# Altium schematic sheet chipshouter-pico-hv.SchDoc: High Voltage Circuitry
size Letter; Organization: NewAE Technology Inc.; Address1: 1083 Queen St., Suite 196; Address2: Halifax; Address3: NS; Address4: Canada B3H 0B2; DocumentNumber: .; Revision: .; SheetNumber: 1; SheetTotal: 2; SheetApproved: YES
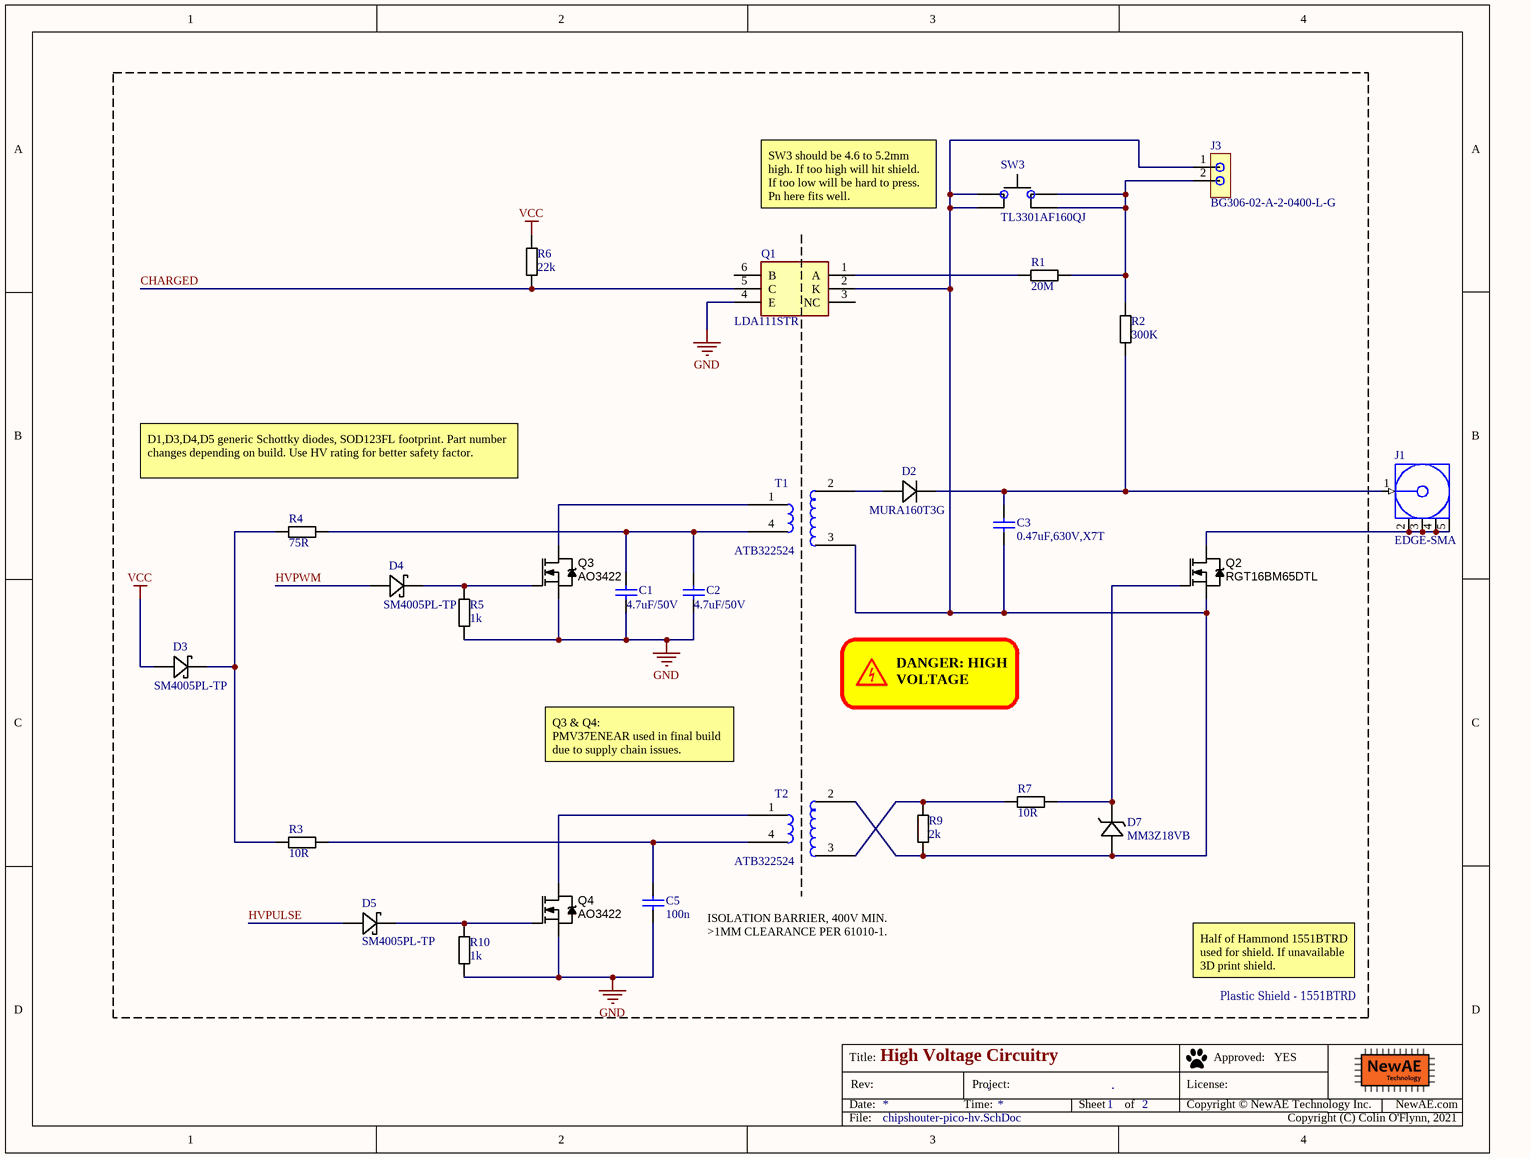
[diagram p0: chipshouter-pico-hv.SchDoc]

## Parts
C1  4.7uF/50V  [CAPC0805_M]
C2  4.7uF/50V  [CAPC0805_M]
C3  0.47uF,630V,X7T  [CKG57N_2220]
C5  100n  [CAPC0603_M]
D2  MURA160T3G  [DO-214AC]
D3  SM4005PL-TP  [DSS13UTR]
D4  SM4005PL-TP  [DSS13UTR]
D5  SM4005PL-TP  [DSS13UTR]
D7  MM3Z18VB  [SOD323]
J1  EDGE-SMA  [CON-SMA-MALE-PCB-EDGE062]
J3  BG306-02-A-2-0400-L-G  [BG306-R2-2PIN]
Q1  LDA111STR  [SOP254P952X470-6N]
Q2  RGT16BM65DTL  [DPAK_TO-252AA_M]
Q3  AO3422  [SOT95P245X110-3M]
Q4  AO3422  [SOT95P245X110-3M]
R1  20M  [RESC5025X06N]
R2  300K  [RESC6432X06N]
R3  10R  [RESC1608X55N]
R4  75R  [RESC2012X70N]
R5  1k  [RESC1608X55N]
R6  22k  [RESC1608X55N]
R7  10R  [RESC1608X55N]
R9  2k  [RESC2012X70N]
R10  1k  [RESC1608X55N]
SW3  TL3301AF160QJ  [CK_KSC7J]
T1  ATB322524  [ATB322524_CHUNKY]
T2  ATB322524  [ATB322524_CHUNKY]

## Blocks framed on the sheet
Plastic Shield - 1551BTRD‎: C1-C3 C5 D2-D5 D7 J3 Q1-Q4 R1-R7 R9 R10 SW3 T1 T2

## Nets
GND: C1.2 C2.2 C5.2 Q1.4(E) Q3.2(S) Q4.2(S) R5.2 R10.2
VCC: D3.A R6.1
CHARGED: Q1.5(C) R6.2
HVPULSE: D5.A
HVPWM: D4.A
NetC1_1: C1.1 C2.1 R4.2 T1.4
NetC3_1: C3.1 D2.K J1.1(Signal) R2.2
NetC3_2: C3.2 D7.A J3.1 Q1.2(K) Q2.2(S) R9.2 SW3.1(IN) SW3.4(IN) T1.3 T2.2
NetC5_1: C5.1 R3.2 T2.4
NetD2_A: D2.A T1.2
NetD3_K: D3.K R3.1 R4.1
NetD4_K: D4.K Q3.1(G) R5.1
NetD5_K: D5.K Q4.1(G) R10.1
NetD7_K: D7.K Q2.1(G) R7.2
NetJ1_2: J1.2(GND) J1.3(GND) J1.4(GND) J1.5(GND) Q2.3(D)
NetJ3_2: J3.2 R1.2 R2.1 SW3.2(IN) SW3.3(IN)
NetQ1_1: Q1.1(A) R1.1
NetQ3_3: Q3.3(D) T1.1
NetQ4_3: Q4.3(D) T2.1
NetR7_1: R7.1 R9.1 T2.3

Not connected (* = marked no-connect by the designer): Q1 3(NC) 6(B)

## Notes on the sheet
- SW3 should be 4.6 to 5.2mm high. If too high will hit shield. If too low will be hard to press. Pn here fits well.
- D1,D3,D4,D5 generic Schottky diodes, SOD123FL footprint. Part number changes depending on build. Use HV rating for better safety factor.
- DANGER: HIGH
  VOLTAGE
- Q3 & Q4:
  PMV37ENEAR used in final build due to supply chain issues.
- ISOLATION BARRIER, 400V MIN.
  >1MM CLEARANCE PER 61010-1.
- Half of Hammond 1551BTRD used for shield. If unavailable 3D print shield.
- Copyright (C) Colin O'Flynn, 2021

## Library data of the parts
C1 C2 = CCHIP-4u7-0805-50V: 4u7, 50V, 0805, Ceramic; Manufacture 1: TDK Corporation; Manufacture Part Number 1: C2012X5R1H475K125AB; Component Group: Capacitor; Value: 4.7uF; Case-EIA: 0805; Case-Metric: 1608; Rated Voltage: 50VDC; Tolerance: 10%
C3 = CKG57NX7T2J105M500JH: 1uF, 630V, X7T, Stacked; Part Number: KRM55TR72J474MH01K; Manufacture 1: TDK Corporation; Component Group: Capacitor; Case-EIA: 2220; Case-Metric: 5750; Tolerance: +22/-30
C5 = CCHIP-100n-0603: 100n, 0603; Manufacture 1: Kemet; Manufacture Part Number 1: C0603C104K5RACTU; Component Group: Capacitor; Case-EIA: 0603; Case-Metric: 1608; Rated Voltage: 50VDC
D2 = MURA160T3G: 600V, 2A, Fast Recovery Diode; Manufacture 1: On Semi
D3-D5 = DSS13UTR: SCHOTTKY 30V SOD-123FL; Manufacture 1: MCC; Component Group: Diode; PP Material Stack: 0
D7 = PDZ10B: DIODE ZENER 10V 400MW SOD323; Manufacture 1: On Semiconductor; Rated Power: 0.4W; Tolerance: 2%; PP Material Stack: 0
J1 = CON-F-SMA-PCBEDGE-003.062: SMA MaleEdge Mount Connector for 0.062" Thick Board; Manufacture 1: Linx Technologies; Manufacture Part Number 1: CONSMA013.062
J3 = BG306-02-A-2-0400-L-G: 2-Pin SMD, Female Header, 0.1" spacing; Manufacture 1: GCT; Component Group: Connector; PP Material Stack: 0
Q1 = LDA111STR: Phototransistor; Manufacturer_Name: IXYS SEMICONDUCTOR
Q2 = IRLR120TRPBF: MOSFET N-CH 100V 7.7A DPAK; Manufacture 1: Vishay Siliconix
Q3 Q4 = DMN3200U-7: MOSFET N-CH 30V 2.2A SOT23-3; Manufacture 1: Diodes Inc.; Rated Power: 3A; PP Material Stack: 0
R1 = RCHIP-20M-2010: 20M, 2010, 1%; Manufacture 1: Vishay; Manufacture Part Number 1: CRMA2010AF20M0FKEF; Component Group: Resistor; Case-EIA: 2010; Case-Metric: 5025; Rated Power: 0.5W; Rated Voltage: 400VDC
R2 = RCHIP-300K-2512: 300K res, 2512, 1%, 3W; Manufacture 1: TE Connectivity; Manufacture Part Number 1: 3522300KFT; Component Group: Resistor; Case-EIA: 2512; Case-Metric: 6432; Rated Voltage: 250V
R3 R7 = RCHIP-10R-0603: 10R res, 0603, 1%, 1/10W; Manufacture 1: Yageo; Manufacture Part Number 1: RC0603FR-0710RL; Component Group: Resistor; Case-EIA: 0603; Case-Metric: 1608; Rated Power: 0.1W; Rated Voltage: 75VDC
R4 = RCHIP-75R-0805: 75R res, 0805, 1%, 1/8W; Manufacture 1: Yageo; Manufacture Part Number 1: RC0805FR-0775RL; Component Group: Resistor; Case-EIA: 0805; Rated Power: 0.125W; Rated Voltage: 75VDC
R5 R10 = RCHIP-1K-0603: 1k res, 0603, 1%, 1/10W; Manufacture 1: Yageo; Manufacture Part Number 1: RC0603FR-071KL; Component Group: Resistor; Case-EIA: 0603; Case-Metric: 1608; Rated Power: 0.1W; Rated Voltage: 75VDC
R6 = RCHIP-22K-0603: 22k res, 0603, 1%, 1/10W; Manufacture 1: Yageo; Manufacture Part Number 1: RC0603FR-0722KL; Component Group: Resistor; Case-EIA: 0603; Case-Metric: 1608; Rated Power: 0.1W; Rated Voltage: 75VDC
R9 = RCHIP-75R-0805: Manufacture 1: Yageo; Manufacture Part Number 1: RC0805FR-0775RL; Component Group: Resistor; Value: 75R; Case-EIA: 0805; Rated Power: 0.125W; Rated Voltage: 75VDC; Tolerance: 1%
SW3 = TACTSW-KSC741J: SWITCH TACTILE SPST-NO 0.01A 32V; Manufacture 1: E-Switch; PP Material Stack: 0
T1 T2 = ATB322524_PROTO: HV Transformer 1:10, Small; Manufacture 1: TDK; Component Group: Inductor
